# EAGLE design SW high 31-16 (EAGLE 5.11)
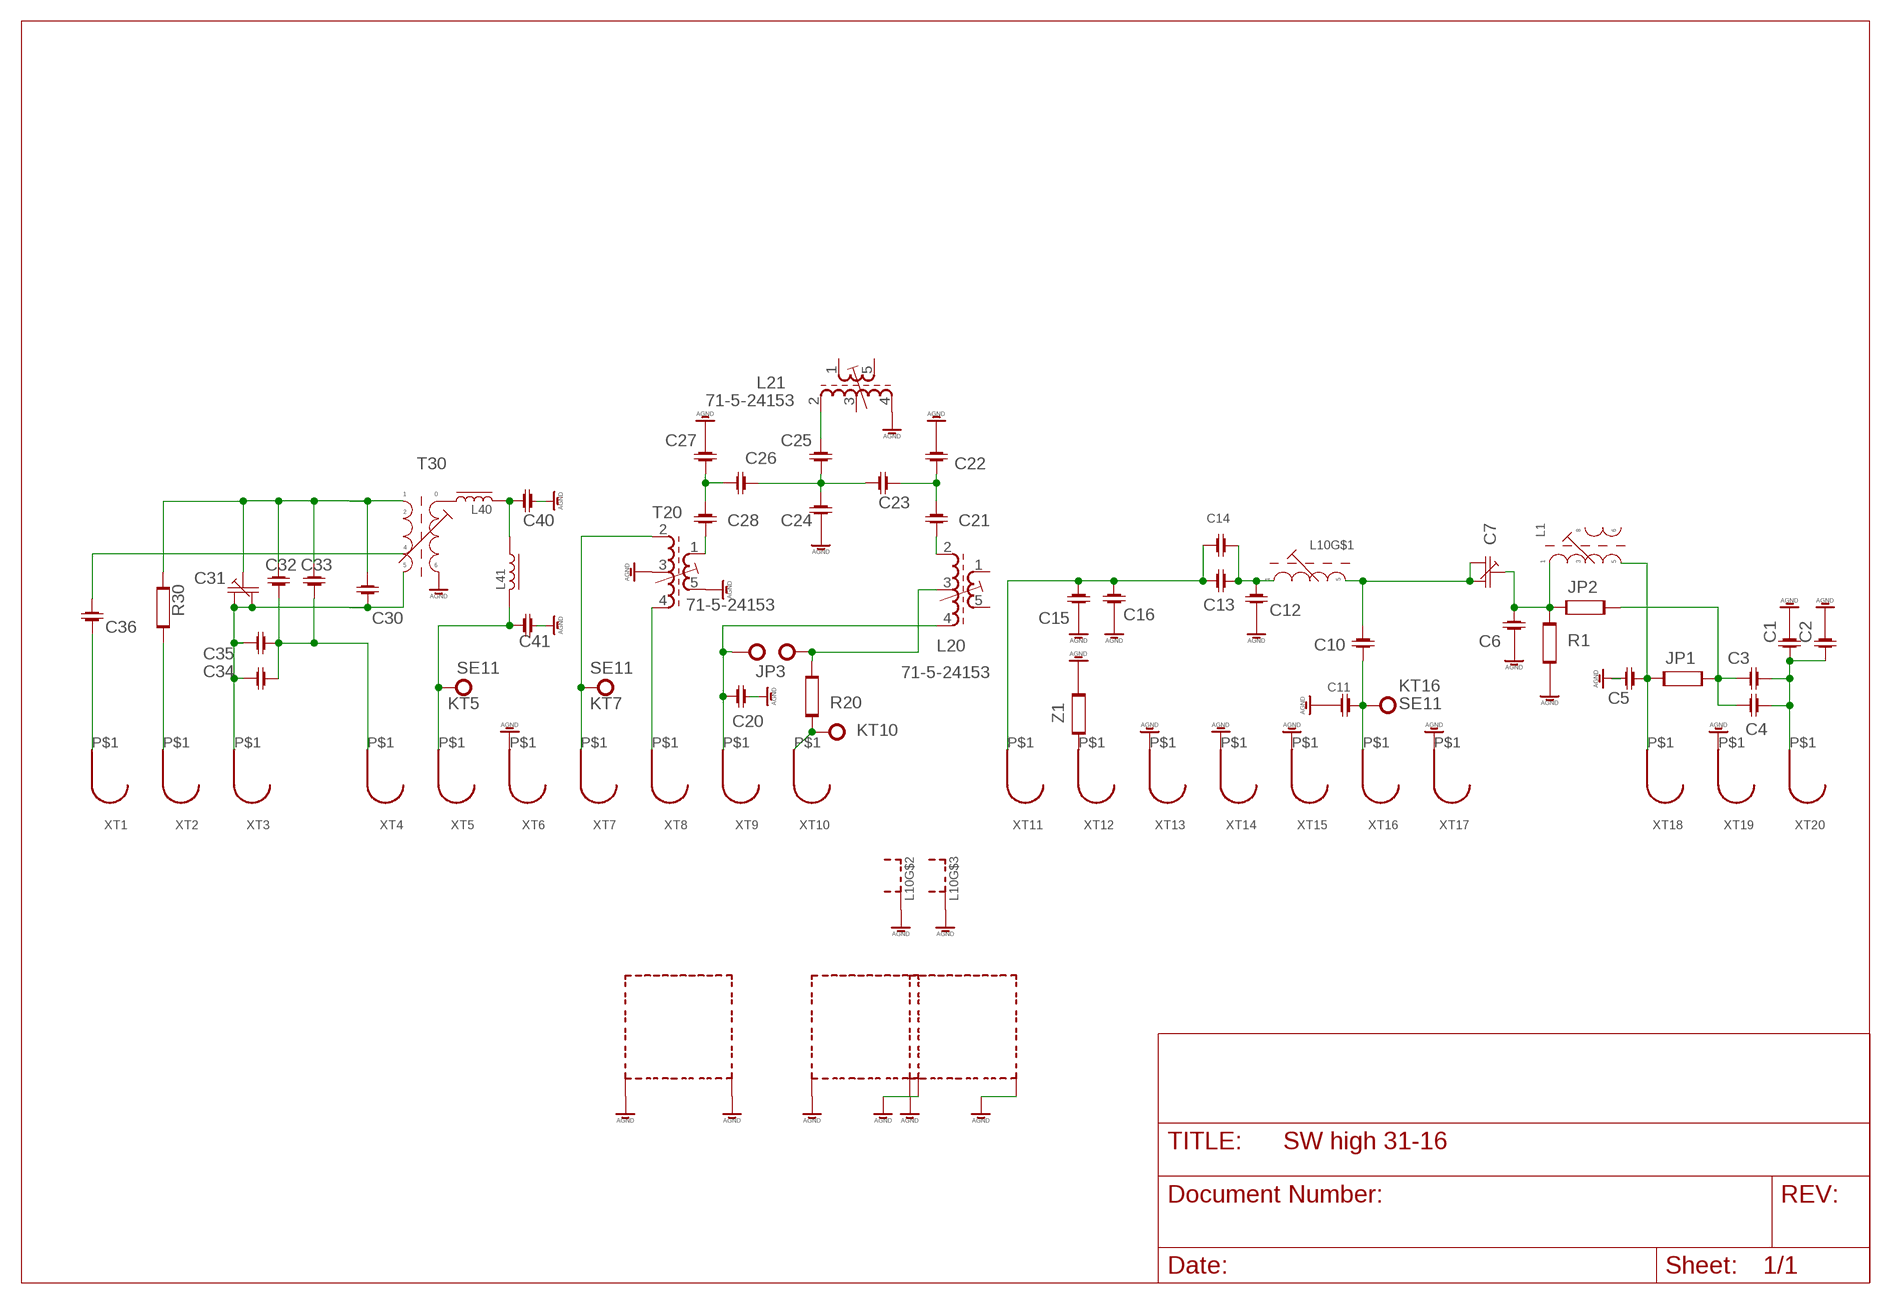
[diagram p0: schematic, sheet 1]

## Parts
C1  C-1206-0805  [RC-SMD-UNIV]
C2  C-1206-0805  [RC-SMD-UNIV]
C3  C-1206-0805  [RC-SMD-UNIV]
C4  C-1206-0805  [RC-SMD-UNIV]
C5  C-1206-0805  [RC-SMD-UNIV]
C6  C-1206-0805  [RC-SMD-UNIV]
C7  C-TRIM-AM  [C-TRIM-ORIG]
C10  C-1206-0805  [RC-SMD-UNIV]
C11  C-1206-0805  [RC-SMD-UNIV]
C12  C-1206-0805  [RC-SMD-UNIV]
C13  C-1206-0805  [RC-SMD-UNIV]
C14  C-1206-0805  [RC-SMD-UNIV]
C15  C-1206-0805  [RC-SMD-UNIV]
C16  C-1206-0805  [RC-SMD-UNIV]
C20  C-1206-0805  [RC-SMD-UNIV]
C21  C-1206-0805  [RC-SMD-UNIV]
C22  C-1206-0805  [RC-SMD-UNIV]
C23  C-1206-0805  [RC-SMD-UNIV]
C24  C-1206-0805  [RC-SMD-UNIV]
C25  C-1206-0805  [RC-SMD-UNIV]
C26  C-1206-0805  [RC-SMD-UNIV]
C27  C-1206-0805  [RC-SMD-UNIV]
C28  C-1206-0805  [RC-SMD-UNIV]
C30  C-1206-0805  [RC-SMD-UNIV]
C31  C-TRIM-AM  [C-TRIM-ORIG]
C32  C-1206-0805  [RC-SMD-UNIV]
C33  C-1206-0805  [RC-SMD-UNIV]
C34  C-1206-0805  [RC-SMD-UNIV]
C35  C-1206-0805  [RC-SMD-UNIV]
C36  C-1206-0805  [RC-SMD-UNIV]
C40  C-1206-0805  [RC-SMD-UNIV]
C41  C-1206-0805  [RC-SMD-UNIV]
JP1  R-1206-0805  [RC-SMD-UNIV]
JP2  R-1206-0805  [RC-SMD-UNIV]
JP3  SE11  [SE11]
KT1  SE11  [SE11]
KT5  SE11  [SE11]
KT7  SE11  [SE11]
KT10  SE11  [SE11]
KT16  SE11  [SE11]
L1  L-MOD-SW-IN-OPEN  [L-KW-LARGE]
L10  L-MOD-SW-GAP  [L-7-MM]
L20  71-5-24153  [71-5]
L21  71-5-24153  [71-5]
L40  L-US0207/10  [0207/10]
L41  L-US0207/10  [0207/10]
R1  R-1206-0805  [RC-SMD-UNIV]
R20  R-1206-0805  [RC-SMD-UNIV]
R30  R-1206-0805  [RC-SMD-UNIV]
T20  71-5-24153  [71-5]
T30  L-MOD-OSC-SW  [L-KW-LARGE]
XT1  CONTACT-RF  [CONTACT-RF]
XT2  CONTACT-RF  [CONTACT-RF]
XT3  CONTACT-RF  [CONTACT-RF]
XT4  CONTACT-RF  [CONTACT-RF]
XT5  CONTACT-RF  [CONTACT-RF]
XT6  CONTACT-RF  [CONTACT-RF]
XT7  CONTACT-RF  [CONTACT-RF]
XT8  CONTACT-RF  [CONTACT-RF]
XT9  CONTACT-RF  [CONTACT-RF]
XT10  CONTACT-RF  [CONTACT-RF]
XT11  CONTACT-RF  [CONTACT-RF]
XT12  CONTACT-RF  [CONTACT-RF]
XT13  CONTACT-RF  [CONTACT-RF]
XT14  CONTACT-RF  [CONTACT-RF]
XT15  CONTACT-RF  [CONTACT-RF]
XT16  CONTACT-RF  [CONTACT-RF]
XT17  CONTACT-RF  [CONTACT-RF]
XT18  CONTACT-RF  [CONTACT-RF]
XT19  CONTACT-RF  [CONTACT-RF]
XT20  CONTACT-RF  [CONTACT-RF]
Z1  R-1206-0805  [RC-SMD-UNIV]

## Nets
AGND: C1.P$2 C2.P$2 C5.P$2 C6.P$2 C11.P$2 C12.P$2 C15.P$1 C16.P$2 C20.P$2 C22.P$2 C24.P$1 C27.P$2 C40.P$1 C41.P$2 L10.P$6(S) L10.P$7(S) L20.S1 L20.S2 L21.4(E1) L21.S1 L21.S2 R1.P$1 T20.3(Z) T20.5(E2) T20.S1 T20.S2 T30.P$2 XT6.P$1 XT13.P$1 XT14.P$1 XT15.P$1 XT17.P$1 XT19.P$1 Z1.P$2
KT1: C10.P$1 C11.P$1 KT16.MP XT16.P$1
N$1: C1.P$1 C2.P$1 C3.P$2 C4.P$2 XT20.P$1
N$2: C3.P$1 C4.P$1 JP1.P$1 JP2.P$1
N$3: C20.P$1 KT1.MP L20.4(E1) XT9.P$1
N$4: C6.P$1 C7.P$5 JP2.P$2 L1.P$3 R1.P$2
N$5: T20.4(E1) XT8.P$1
N$6: C7.P$6 C7.P$7 C10.P$2 L10.3
N$7: C12.P$1 C13.P$1 C14.P$2 L10.1
N$8: C5.P$1 JP1.P$2 L1.P$1 XT18.P$1
N$9: JP3.MP L20.3(Z) R20.P$1
N$10: XT12.P$1 Z1.P$1
N$11: KT10.MP R20.P$2 XT10.P$1
N$12: C13.P$2 C14.P$1 C15.P$2 C16.P$1 XT11.P$1
N$13: KT7.MP T20.2(A1) XT7.P$1
N$14: C28.P$1 T20.1(A2)
N$15: C26.P$2 C27.P$1 C28.P$2
N$16: R30.P$2 XT2.P$1
N$18: L40.1 T30.P$3
N$19: C23.P$2 C24.P$2 C25.P$1 C26.P$1
N$20: C30.P$2 C31.P$6 C31.P$7 C34.P$2 C35.P$2 T30.P$6 XT3.P$1
N$21: C32.P$2 C33.P$2 C34.P$1 C35.P$1 XT4.P$1
N$22: C30.P$1 C31.P$5 C32.P$1 C33.P$1 R30.P$1 T30.P$5
N$23: C41.P$1 KT5.MP L41.2 XT5.P$1
N$24: C36.P$1 T30.P$4
N$25: C40.P$2 L40.2 L41.1
N$26: C36.P$2 XT1.P$1
N$29: C21.P$2 C22.P$1 C23.P$1
N$30: C21.P$1 L20.2(A1)
N$31: C25.P$2 L21.2(A1)
Unconnected: L1.P$2 L1.P$5 L1.P$6 L20.1(A2) L20.5(E2) L21.1(A2) L21.3(Z) L21.5(E2) T30.P$1

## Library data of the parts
C1-C6 C10-C16 C20-C28 C30 C32-C36 C40 C41 = OKEAH:C-1206-0805
C7 C31 = OKEAH:C-TRIM-AM
JP1 JP2 R1 R20 R30 Z1 = OKEAH:R-1206-0805
JP3 KT1 KT5 KT7 KT10 KT16 = solpad:SE11: SOLDER PAD
L1 = OKEAH:L-MOD-SW-IN-OPEN
L10 = OKEAH:L-MOD-SW-GAP
L20 L21 T20 = L NEOSID:71-5-: TRANSFORMER adjustable filter transformer with tap; OC_FARNELL: unknown; OC_NEWARK: unknown
L40 L41 = rcl:L-US: INDUCTOR, American symbol
T30 = OKEAH:L-MOD-OSC-SW
XT1-XT20 = OKEAH:CONTACT-RF

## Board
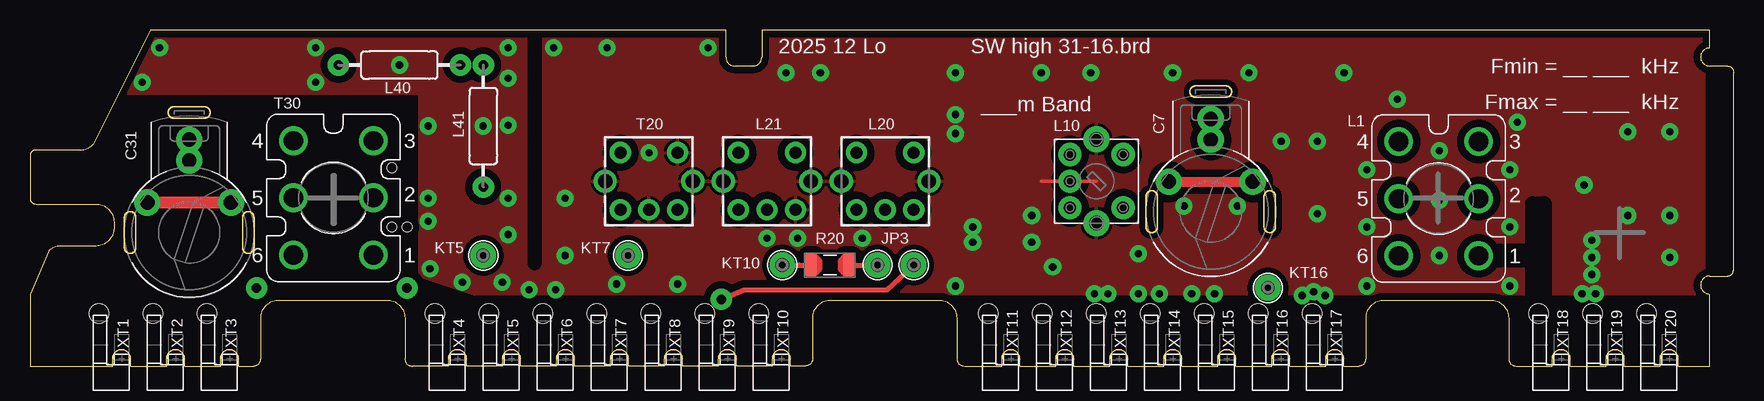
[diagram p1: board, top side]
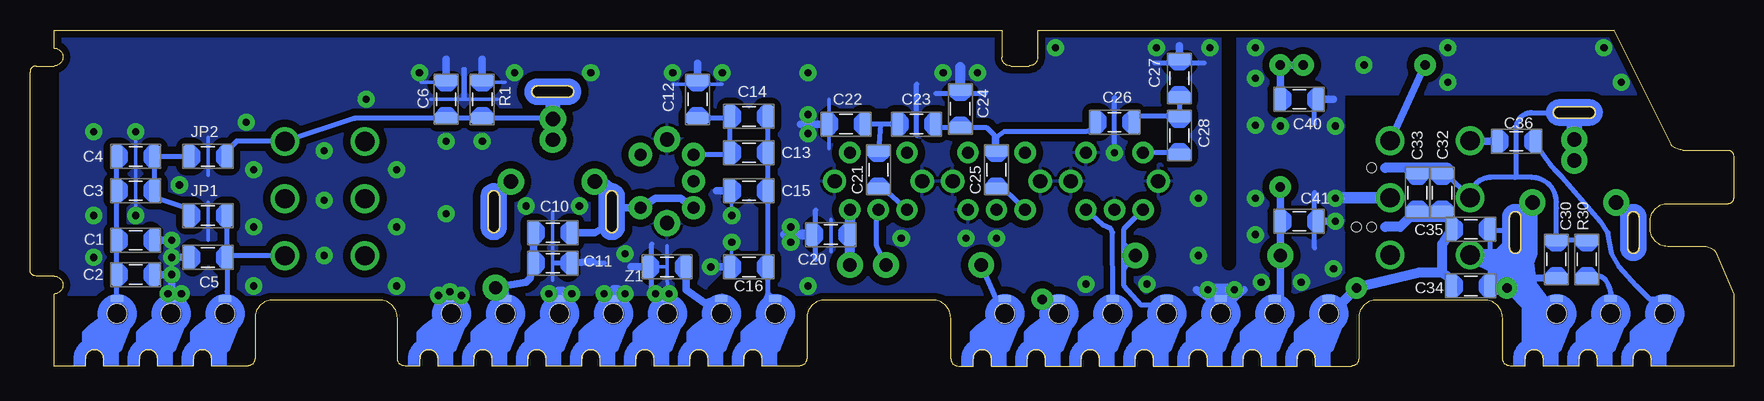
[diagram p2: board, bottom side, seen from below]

Size 142 x 28 mm. Coordinates in mm from the lower left corner, seen from the top.
Outline: 135 segments
Copper layers (1*16): Top 0.035mm / dielectric 1.5mm / Bottom 0.035mm
Design rules "default *": minimum track width 10mil, minimum drill 24mil, track to track 8mil, track to pad 8mil, pad to pad 8mil, via to via 8mil, smd to smd 8mil, copper to edge 8mil, drill to drill 8mil, minimum pad ring 10mil, minimum via ring 8mil, stop-mask expansion 4mil, vias tented up to drill 0mil, thermal gap 10mil
Holes 0.8 mm at 30.16,16.51 30.16,11.59 31.43,11.59
tRestrict: 10 lines
bRestrict: 22 lines

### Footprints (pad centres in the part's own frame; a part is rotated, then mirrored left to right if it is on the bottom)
RC-SMD-UNIV = smd 0.965 x 1.93: P$1 -1.587,0; P$2 1.587,0
C-TRIM-ORIG = drill 1.2 pad 2.184 round: P$4 7.739,0; P$5 5.992,0; P$6 2.5,3.493; P$7 2.5,-3.493
SE11 = drill 1.1 pad 2.159 round: MP 0,0
L-KW-LARGE = drill 1.6 round: P$1 0,0; P$2 0,4.763; P$3 0,9.525; P$4 -6.668,9.525; P$5 -6.668,4.763; P$6 -6.668,0
L-7-MM = drill 1 pad 1.93 round: 1 -2.223,-2.223; 2 0,-2.223; 3 2.223,-2.223; 4 2.223,2.223; 5 -2.223,2.223 | drill 1.2 pad 2.184 round: P$6 3.493,0; P$7 -3.493,0
71-5 = drill 1 pad 1.778 round: 1 2.381,-2.381; 2 2.381,2.381; 3 0,2.381; 4 -2.381,2.381; 5 -2.381,-2.381 | drill 1.2 pad 1.93 round: S1 -3.651,0; S2 3.651,0
0207/10 = drill 0.8 pad 1.778 round: 1 -5.08,0; 2 5.08,0
CONTACT-RF = smd 1.016 x 0.508 bottom: P$1 1,-5.625 | hole 1.6: 1,-4.375

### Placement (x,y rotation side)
C1  133.19,10.48 0 bottom
C2  133.19,7.62 0 bottom
C3  133.19,14.61 180 bottom
C4  133.19,17.46 180 bottom
C5  127.16,9.05 180 bottom
C6  107.31,22.23 90 bottom
C7  98.42,12.86 90 top
C10  98.42,11.11 0 bottom
C11  98.42,8.57 0 bottom
C12  86.36,22.23 90 bottom
C13  82.07,17.78 0 bottom
C14  82.07,20.8 180 bottom
C15  82.07,14.61 0 bottom
C16  82.07,8.26 180 bottom
C20  75.25,10.96 180 bottom
C21  71.28,16.35 90 bottom
C22  73.98,20.16 180 bottom
C23  68.1,20.16 0 bottom
C24  64.45,21.43 270 bottom
C25  61.44,16.35 270 bottom
C26  51.59,20.32 0 bottom
C27  46.2,23.97 90 bottom
C28  46.2,19.21 90 bottom
C30  14.76,8.89 270 bottom
C31  13.27,11.13 90 top
C32  24.29,14.45 270 bottom
C33  26.35,14.45 270 bottom
C34  21.91,6.67 0 bottom
C35  21.9,11.4 0 bottom
C36  18.1,18.73 0 bottom
C40  36.2,22.23 180 bottom
C41  36.2,12.07 0 bottom
JP1  127.16,12.54 0 bottom
JP2  127.16,17.46 0 bottom
JP3  70.64,8.42 0 top
KT1  73.66,8.42 0 top
KT5  37.78,9.21 0 top
KT7  49.85,9.21 0 top
KT10  62.71,8.42 0 top
KT16  103.19,6.51 0 top
L1  120.75,9.19 0 top
L10  88.9,15.4 270 top
L20  71.28,15.4 180 top
L21  61.44,15.4 180 top
L40  30.8,25.08 0 top
L41  37.78,20 270 top
R1  104.3,22.23 270 bottom
R20  66.68,8.42 180 top
R30  12.22,8.89 270 bottom
T20  51.59,15.4 180 top
T30  28.62,9.25 0 top
XT1  6.75,0 180 top
XT2  11.25,0 180 top
XT3  15.75,0 180 top
XT4  34.75,0 180 top
XT5  39.25,0 180 top
XT6  43.75,0 180 top
XT7  48.25,0 180 top
XT8  52.75,0 180 top
XT9  57.25,0 180 top
XT10  61.75,0 180 top
XT11  80.88,0 180 top
XT12  85.38,0 180 top
XT13  89.88,0 180 top
XT14  94.38,0 180 top
XT15  98.88,0 180 top
XT16  103.38,0 180 top
XT17  107.88,0 180 top
XT18  126.75,0 180 top
XT19  131.25,0 180 top
XT20  135.75,0 180 top
Z1  88.9,8.26 180 bottom

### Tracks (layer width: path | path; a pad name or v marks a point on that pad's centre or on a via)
AGND  (via drill 0.6 pad 1.42)
  Top 0.305: 84.3,15.4 88.9,15.4
  Bottom 0.127: 83.5,15.24 C15.P$1
  Bottom 0.305: v107,6.19 v107.95,5.88 | v88.74,6.03 88.9,7.15 88.9,10 | 75.25,9.53 75.25,12.23 | v83.5,12.54 83.5,15.24 | 83.5,7.78 83.5,10.48 | 75.41,18.1 75.41,22.23 | 84.3,23.5 88.42,23.5 | 91.76,8.26 88.9,8.26 | 98.42,7.15 98.42,12.86 | 102.39,23.66 104.93,23.66 | 106.52,23.66 109.38,23.66 | 103.03,22.23 108.58,22.23 | 133.19,13.18 133.19,18.74 | 127.16,15.88 127.16,19.05 | 127.16,10.48 127.16,13.66 | 105.73,22.23 105.73,24.77 | 105.89,22.23 105.89,24.77
  Bottom 0.406: XT17.P$1 v107,6.19 | 34.92,20.16 34.92,22.39 | 34.92,12.54 34.92,14.45 | 34.92,12.54 34.92,11.91 | 34.92,9.84 34.92,12.54 | 76.52,8.89 76.52,13.02 | 44.13,25.24 48.26,25.24 | 62.39,22.7 66.52,22.7 | 90.17,6.04 90.17,10.16 | 94.14,8.57 98.27,8.57 | 51.59,18.26 51.59,22.39 | 68.1,19.21 68.1,23.5
  Bottom 0.61: 44.77,6.35 43.66,5.56 XT6.P$1 41.91,5.4 40.8,6.35 | C41.P$2 33.34,12.07 | C40.P$1 33.34,22.23 | C27.P$2 46.2,26.67 | C22.P$2 77.79,20.16 | Z1.P$2 91.76,8.26 91.92,8.26 | XT13.P$1 v88.74,6.03 | C15.P$1 84.77,14.61 | C16.P$2 v85.25,8.26 | C12.P$2 86.36,25.24 | 95.09,8.73 C11.P$2 | C6.P$2 107.31,25.56 | R1.P$1 104.3,25.56 | C5.P$2 v130.18,9.05 | C2.P$2 v130.18,7.62 130.18,5.72 XT19.P$1 | C1.P$2 v130.18,10.48
  Bottom 0.813: XT14.P$1 93.34,5.72 93.34,6.35 93.03,6.35 v92.39,6.03 | XT15.P$1 97.63,6.19 97.95,6.19 97.79,5.72 v96.84,6.03 | C20.P$2 79.06,10.96 | C24.P$1 64.45,24.93
  Bottom 1.016: T30.P$2 v33.18,13.97 | v41.59,6.35 v43.81,6.35
  other vias: 33.18,20 37.78,20 30.8,25.08 10.79,26.51 23.81,26.51 23.81,23.66 106.05,5.88 9.37,23.66 63.98,10.64 39.85,26.51 39.85,13.97 33.34,8.1 78.58,10.32 77.15,6.67 39.84,20.08 69.37,10.64 111.44,16.35 100.65,13.34 39.37,6.99 94.14,6.03 98.74,6.03 39.85,23.97 111.44,11.59 123.35,16.35 36.04,6.99 48.9,6.83 53.98,6.83 61.44,10.64 65.88,24.45 78.58,11.59 44.61,9.21 44.61,13.97 48.1,26.51 77.15,20.96 43.66,26.51 56.51,26.51 77.15,24.45 51.59,17.78 63.02,24.45 95.25,24.45 89.85,6.03 77.15,19.37 84.3,24.45 88.42,24.45 101.6,24.45 83.5,10.32 92.39,9.37 123.35,11.59 117.47,13.81 130.49,6.03 129.38,6.03 136.68,9.05 133.19,12.54 136.68,12.54 129.54,15.08 133.19,19.53 136.68,19.53 123.98,20.32 117.47,17.94 117.47,9.21 109.54,24.45 104.3,18.73 107.31,18.73 113.98,22.23 107.31,12.7 111.44,6.67 123.35,6.67 96.2,13.34 33.18,12.07 39.85,10.96
  pour Top (isolate 0.61): 37,6 32.5,7.5 32.5,22.68 7.5,22.68 10,28 58,28 58,25 61,25 61,28 139.5,28 139.5,6
  pour Bottom (isolate 0.61): 10,28 139.5,28 139.5,6 37,6 32.5,7.5 32.5,22.68 7.5,22.68
KT1
  Bottom 0.406: XT16.P$1 102.39,5.63
  Bottom 0.61: 102.39,6.67 KT16.MP | 102.39,6.67 XT16.P$1 | C10.P$1 C11.P$1 100.17,7.94 100.33,7.31 100.65,6.99 102.39,6.67
N$1
  Bottom 0.406: XT20.P$1 134.78,5.72 C2.P$1 C1.P$1 C3.P$2 C4.P$2
N$2
  Bottom 0.406: JP2.P$1 C4.P$1 C3.P$1 131.44,13.97 129.06,13.18 JP1.P$1
N$3  (via drill 0.8 pad 1.78)
  Top 0.406: v57.63,5.56 59.53,6.35 71.44,6.35 73.5,8.26 KT1.MP
  Bottom 0.406: XT9.P$1 v57.63,5.56
  Bottom 0.813: 73.66,12.23 C20.P$1 | 73.66,12.23 L20.4 | KT1.MP 73.66,12.23
N$4
  Bottom 0.406: C7.P$5 98.42,20.64 R1.P$2 C6.P$1 114.94,20.64 L1.P$3 124.78,18.74 125.41,18.1 JP2.P$2
N$5
  Bottom 0.406: T20.4 52.55,11.75 51.91,11.43 51.75,11.12 XT8.P$1
N$6
  Top 0.406: C7.P$6 C7.P$7
  Bottom 0.305: 94.3,11.43 93.98,10.96 93.5,10.8 93.34,10.8 93.03,10.96 92.71,11.27 92.71,12.39 92.55,13.18
  Bottom 0.406: 92.55,13.18 92.71,14.29 93.03,14.77 93.34,14.92 94.14,15.56 C7.P$6
  Bottom 0.61: L10.3 87.79,13.97 89.85,13.97 91.12,13.18 92.55,13.18 | C10.P$2 94.93,11.12 94.3,11.43
N$7
  Bottom 0.406: L10.1 83.98,17.62 C13.P$1 C14.P$2 83.98,20.64 C12.P$1
N$8
  Bottom 0.406: 125.57,9.21 C5.P$1 | 125.57,9.21 JP1.P$2 | 125.57,9.21 C5.P$1 | L1.P$1 125.57,9.21 | C5.P$1 125.57,6.19 125.57,5.72 XT18.P$1
N$9
  Top 0.406: R20.P$1 JP3.MP
  Bottom 0.406: JP3.MP 71.44,10 71.44,13.02 L20.3
N$10
  Bottom 0.61: XT12.P$1 84.3,5.63 84.3,5.72 85.25,5.4 85.72,5.24 87.31,6.35 Z1.P$1
N$11
  Top 0.406: KT10.MP 64.14,8.42 64.61,8.42 R20.P$2
  Bottom 0.406: KT10.MP 61.44,5.56 XT10.P$1
N$12
  Bottom 0.406: XT11.P$1 80.64,5.56 80.49,6.03 | 80.49,6.03 80.01,5.72 80.49,6.03 | 80.49,6.03 C16.P$1 C15.P$2 C13.P$2 C14.P$1
N$13
  Bottom 0.406: 50.8,10.16 KT7.MP 50.8,8.1 | 50.8,10.16 50.8,11.43 T20.2 | XT7.P$1 48.26,5.08 49.37,5.08 50.8,6.67 50.8,8.1 | 50.8,8.1 50.8,10.16
N$14
  Bottom 0.406: T20.1 46.99,17.78 C28.P$1
N$15
  Bottom 0.406: C27.P$1 C28.P$2 50.01,20.8 C26.P$2 | C26.P$2
N$16
  Bottom 0.406: XT2.P$1 10.16,5.72 arc-37 10.79,7.31 arc-52 11.75,7.46 arc-21 R30.P$2
N$17
  Bottom 0.813: 23.81,16.35 23.81,16.51 29.05,16.51
N$18
  Bottom 0.61: T30.P$3 L40.1
N$19
  Bottom 0.406: 66.2,19.85 C24.P$2 62.23,19.85 61.59,19.21 61.59,18.26 61.91,18.1 C25.P$1 61.44,19.05 60.8,19.53 53.98,19.53 53.5,19.69 C26.P$1 | 66.2,19.85 | 66.2,19.85 C23.P$2
N$20
  Top 1.016: C31.P$7 C31.P$6
  Bottom 0.406: 15.88,4.77 16.51,4.77 | 19.84,9.22 19.84,9.37 19.05,10.16 19.05,11.27 20.18,11.27 C35.P$2 C34.P$2
  Bottom 0.61: XT3.P$1 15.56,5.4 15.88,4.77 | 16.95,7.36 C30.P$2
  Bottom 1.016: C31.P$6 9.05,13.18 | 16.51,4.77 15.88,5.4 16.83,6.67 16.82,6.51 16.95,7.36 17.12,8.57 | 17.12,8.57 16.83,9.37 16.83,13.63 C31.P$7 | T30.P$6 19.84,9.22 19.37,9.21 19.37,8.57 17.12,8.57
  Bottom 1.27: 16.82,6.51 20.16,6.51
N$21  (via drill 0.8 pad 1.78)
  Bottom 0.406: C34.P$1 23.65,7.31 | XT4.P$1 32.7,5.24 v31.43,6.51
  Bottom 0.61: C35.P$1 23.81,12.86 C32.P$2 C33.P$2
  Bottom 0.813: C35.P$1 24.29,10.16 24.29,7.78 | 23.65,7.31 24.29,7.78 | 32.7,5.24 v31.43,6.51 26.19,7.78 24.29,7.78 | C32.P$2 24.29,12.7 23.97,12.39 26.99,12.39 | 26.99,12.39 | 26.99,12.39 27.78,11.59 29.05,11.59
N$22
  Bottom 0.406: 18.26,15.72 16.83,15.72 arc90 14.76,13.66 14.76,13.18 C30.P$1 R30.P$1 | 18.26,15.72 20.25,15.72 arc-90 T30.P$5 23.89,15.94 arc-45 24.11,16.04 C32.P$1 | C31.P$5 13.27,20.17 arc-45 13.34,20.32 14.79,20.32 arc45 15.02,20.42 15.24,20.64 15.24,20.83 arc-45 15.33,21.05 15.4,21.12 16.83,21.12 arc-90 18.1,19.85 18.1,15.88 arc90 18.26,15.72
  Bottom 0.61: C32.P$1 24.77,16.19 25.72,16.19 C33.P$1
N$23
  Bottom 0.61: L41.2 C41.P$1 KT5.MP | KT5.MP 37.78,5.72 XT5.P$1 | KT5.MP 37.78,6.35
N$24
  Bottom 0.61: C36.P$1 20.95,18.74 T30.P$4
N$25
  Bottom 0.61: C40.P$2 L41.1 L40.2
N$26
  Bottom 0.406: XT1.P$1 6.35,5.56 6.85,5.56 arc45 7.08,5.65 8.1,6.67 9.53,8.26 10.16,9.37 10.48,11.12 11.11,12.07 14.29,15.72 arc13 16.19,18.1 arc12 C36.P$2
N$27  (via drill 0.8 pad 1.78)
  Bottom 0.406: v18.89,6.51 19.37,6.51 19.37,6.99
  Bottom 1.016: 18.41,6.35 19.21,8.42 21.91,9.21 19.68,8.1 19.37,6.99 19.37,8.89 18.73,7.62 17.14,7.62 17.14,5.08 | 18.41,6.35 17.14,6.35 16.51,3.81 17.14,2.86 17.14,5.08 | 17.14,5.08 18.41,6.35
N$29
  Bottom 0.406: 71.12,20.16 C23.P$1 71.12,20.16 | 71.12,20.16 C22.P$1 | 71.12,20.16 C21.P$2
N$30
  Bottom 0.406: L20.2 70.48,14.45 70.64,14.61 70.96,14.77 C21.P$1
N$31
  Bottom 0.406: L21.2 60.17,14.13 | 60.17,14.13 | 60.17,14.13 60.96,14.77 C25.P$2

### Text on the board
tPlace: 2025 12 Lo | SW high 31-16.brd | Fmin = __ ___ kHz | Fmax = __ ___ kHz | ___m Band
tDocu: ANT Modul | grid placement = 0.125mm | grid placement = 0.125mm | grid SMD = 0.3175mm | grid SMD = 0.3175mm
